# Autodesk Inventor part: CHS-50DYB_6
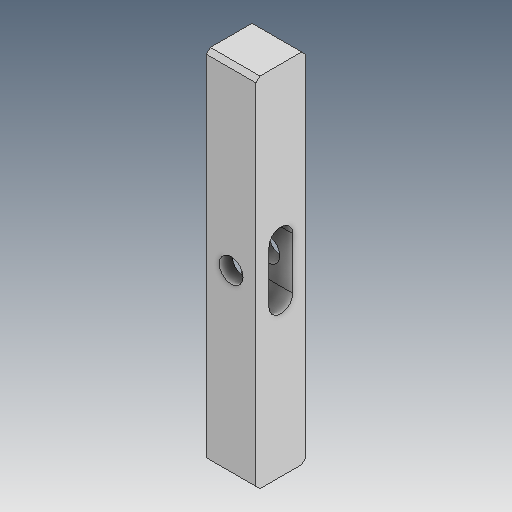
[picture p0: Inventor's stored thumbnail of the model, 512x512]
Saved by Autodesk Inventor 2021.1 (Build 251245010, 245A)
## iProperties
Created: 2019-04
Part Number: CHS-50DYB_6
Material: Ogólny
Document SubType Name: Modeling
Designer: user
Density: 1 g/cm^3
Appearance: Domyślna
Author: user
Revision Number: ÈÎºÎ
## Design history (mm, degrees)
feature "ÊäÈë1"
node "Bryła1"
